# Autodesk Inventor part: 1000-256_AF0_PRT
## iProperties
Created: 2007-03
Part Number: 1000-256_AF0_PRT
Document SubType Name: Modeling
Designer: Andy Moles
Material: Steel
Mass: 20.4745 g
Surface Area: 20.9331 cm^2
Volume: 2.60821 cm^3
Density: 7.85 g/cm^3
Author: Andy Moles
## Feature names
1. Base1
